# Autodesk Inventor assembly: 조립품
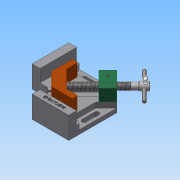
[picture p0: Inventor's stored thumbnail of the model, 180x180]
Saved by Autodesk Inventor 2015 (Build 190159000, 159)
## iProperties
Created: 2019-04
Part Number: 조립품
Document SubType Name: Assembly
Designer: user
Author: user
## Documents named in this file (11)
- C:\Users\user\Desktop\490407V1034\조립품.iam
- C:\Users\user\Desktop\490407V1034\본체.ipt
- C:\Users\user\Desktop\490407V1034\서포트.ipt
- C:\Users\user\Desktop\490407V1034\부시.ipt
- C:\Users\user\Desktop\490407V1034\리드스크류.ipt
- C:\Users\user\Desktop\490407V1034\조.ipt
- C:\Users\user\Desktop\490407V1034\핸들.ipt
- C:\Users\user\Desktop\490407V1034\평행 핀 2.5x24.ipt
- C:\Users\user\Desktop\490407V1034\멈춤나사 M4x10.ipt
- C:\Users\user\Desktop\490407V1034\멈춤나사 M4x5.ipt
- C:\Users\user\Desktop\490407V1034\볼트 M4x16.ipt
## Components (1 placed, 1 different names)
1. 핸들:1
